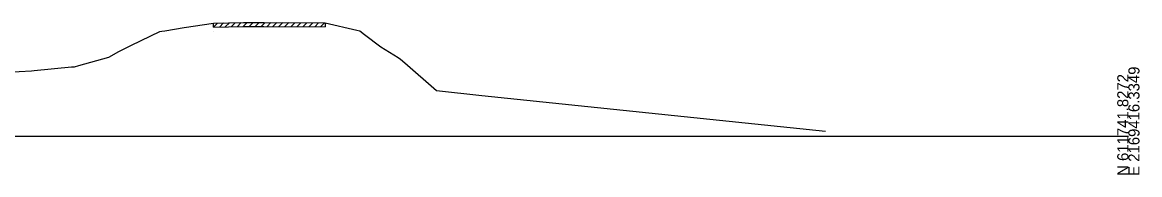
# Model space of a CAD drawing. Extents: x -26 to 6803, y -10 to 19606.
# Drawn here: x 2521.5 to 2802.8, y 5490.3 to 5528.6 of the extents above; entities that cross this region are included whole.
import ezdxf

# ---------------------------------------------------------------- set-up
doc = ezdxf.new("R2010")
doc.units = 0
for name, color, linetype in [('RD_GPK_XS_Cell', 7, 'Continuous'), ('RD_XS_ExGround', 7, 'Continuous'), ('RD_XS_ExPaveRet', 7, 'Continuous'), ('RD_XS_Milling', 7, 'Continuous')]:
    doc.layers.add(name, color=color, linetype=linetype)

msp = doc.modelspace()

# ---------------------------------------------------------------- linework, layer by layer
at = {"layer": 'RD_GPK_XS_Cell'}
msp.add_line((2400, 5500), (2800, 5500), dxfattribs=at)
at = {"layer": 'RD_XS_ExGround'}
msp.add_lwpolyline([(2517.63, 5516.08), (2523.78, 5516.43), (2524.49, 5516.5), (2533.92, 5517.38), (2534.62, 5517.43), (2535.78, 5517.73), (2543.28, 5519.86), (2545.81, 5521.27), (2548.97, 5522.9), (2556.1, 5526.31), (2556.63, 5526.42), (2557.38, 5526.49), (2562.3, 5527.29), (2569.62, 5528.4), (2577.18, 5528.54), (2580.15, 5528.6), (2582.29, 5528.58), (2597.78, 5528.45), (2605.75, 5526.63), (2606.49, 5526.5), (2607.69, 5525.59), (2611.75, 5522.48), (2616.17, 5519.77), (2616.75, 5519.38), (2617.86, 5518.43), (2625.82, 5511.47), (2637.24, 5510.23), (2723.75, 5501.23)], dxfattribs=at)
at = {"layer": 'RD_XS_ExPaveRet'}
for p, q in [((2569.62, 5527.4), (2570.64, 5528.42)), ((2569.62, 5527.4), (2569.62, 5528.4)), ((2571.12, 5527.43), (2572.14, 5528.45)), ((2572.62, 5527.46), (2573.64, 5528.48)), ((2574.12, 5527.49), (2575.14, 5528.51)), ((2575.62, 5527.51), (2576.64, 5528.53)), ((2577.12, 5527.54), (2578.14, 5528.56)), ((2578.62, 5527.57), (2579.64, 5528.59)), ((2580.12, 5527.6), (2581.12, 5528.59)), ((2581.62, 5527.59), (2582.62, 5528.58)), ((2583.12, 5527.58), (2584.12, 5528.57)), ((2584.62, 5527.56), (2585.62, 5528.55)), ((2586.12, 5527.55), (2587.12, 5528.54)), ((2587.62, 5527.54), (2588.62, 5528.53)), ((2589.12, 5527.52), (2590.12, 5528.52)), ((2590.62, 5527.51), (2591.62, 5528.5)), ((2592.12, 5527.5), (2593.12, 5528.49)), ((2593.62, 5527.49), (2594.62, 5528.48)), ((2595.12, 5527.47), (2596.12, 5528.46)), ((2596.62, 5527.46), (2597.62, 5528.45)), ((2597.78, 5528.45), (2597.78, 5527.45)), ((2569.62, 5527.4), (2577.18, 5527.54)), ((2569.62, 5527.4), (2569.62, 5527.4)), ((2577.18, 5527.54), (2580.15, 5527.6)), ((2580.15, 5527.6), (2582.29, 5527.58)), ((2582.29, 5527.58), (2597.78, 5527.45))]:
    msp.add_line(p, q, dxfattribs=at)
at = {"layer": 'RD_XS_Milling'}
msp.add_line((2569.62, 5526.4), (2569.62, 5526.4), dxfattribs=at)
msp.add_line((2569.62, 5526.4), (2569.62, 5526.4), dxfattribs=at)

# ---------------------------------------------------------------- texts
at = {"layer": 'RD_GPK_XS_Cell'}
for s, p in [('E 2169416.3349', (2802.8, 5490)), ('N 611741.8272', (2800, 5490))]:
    msp.add_text(s, height=2.8, rotation=90, dxfattribs=at).set_placement(p)

doc.saveas('drawing.dxf')
